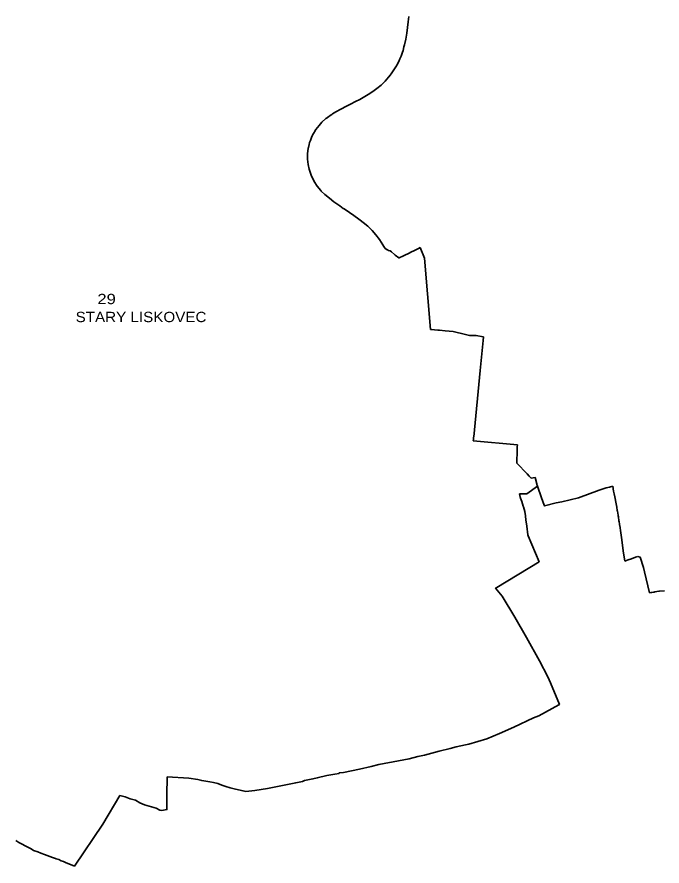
# Model space of a CAD drawing. Extents: x -610940 to -588976, y -1170376 to -1149800.
# Drawn here: x -602206 to -600644, y -1165123 to -1163066 of the extents above; entities that cross this region are included whole.
import ezdxf

# ---------------------------------------------------------------- set-up
doc = ezdxf.new("R2010")
doc.units = 0
doc.header["$LTSCALE"] = 10
doc.layers.add('54', color=7, linetype='Continuous', lineweight=35)
doc.layers.add('55', color=7, linetype='Continuous')
doc.layers.add('56', color=7, linetype='Continuous')

msp = doc.modelspace()

# ---------------------------------------------------------------- linework, layer by layer
at = {"layer": '54'}
for p, q in [((-601281.72, -1163174.04), (-601278.79, -1163167.7)), ((-601298.34, -1163201.91), (-601288.58, -1163187.04)), ((-601314.84, -1163221.81), (-601306.58, -1163212.44)), ((-601306.58, -1163212.44), (-601305.86, -1163211.62)), ((-601305.86, -1163211.62), (-601302.39, -1163207.25)), ((-601302.39, -1163207.25), (-601299.9, -1163204.11)), ((-601299.9, -1163204.11), (-601298.34, -1163201.91)), ((-601334.39, -1163239.6), (-601324.44, -1163231.2)), ((-601324.44, -1163231.2), (-601314.84, -1163221.81)), ((-601376.17, -1163266.1), (-601355.57, -1163254.24)), ((-601355.57, -1163254.24), (-601344.5, -1163247.04)), ((-601344.5, -1163247.04), (-601334.39, -1163239.6)), ((-601410.02, -1163283.2), (-601398.66, -1163277.5)), ((-601398.66, -1163277.5), (-601386.42, -1163271.38)), ((-601386.42, -1163271.38), (-601376.17, -1163266.1)), ((-601441.93, -1163301.26), (-601433.77, -1163296.19)), ((-601433.77, -1163296.19), (-601422.25, -1163289.51)), ((-601422.25, -1163289.51), (-601420.58, -1163288.65)), ((-601420.58, -1163288.65), (-601410.02, -1163283.2)), ((-601474.67, -1163328.87), (-601467.67, -1163321.28)), ((-601467.67, -1163321.28), (-601457.87, -1163312.46)), ((-601457.87, -1163312.46), (-601455.31, -1163310.61)), ((-601495.45, -1163365.24), (-601492.96, -1163358.42)), ((-601492.96, -1163358.42), (-601490.12, -1163352.23)), ((-601490.12, -1163352.23), (-601489.4, -1163350.88)), ((-601486.71, -1163345.94), (-601485.62, -1163344.36)), ((-601497.37, -1163370.7), (-601495.45, -1163365.24)), ((-601502.35, -1163397.75), (-601500.61, -1163383.76)), ((-601502.35, -1163397.75), (-601502.2, -1163411.04)), ((-601502.2, -1163411.04), (-601500.71, -1163424.06)), ((-601500.71, -1163424.06), (-601498.32, -1163435.22)), ((-601498.32, -1163435.22), (-601493.67, -1163449.65)), ((-601493.67, -1163449.65), (-601486.56, -1163464.53)), ((-601486.56, -1163464.53), (-601479.17, -1163475.92)), ((-601479.17, -1163475.92), (-601470.51, -1163486.67)), ((-601460.45, -1163496.63), (-601449.66, -1163505.62)), ((-601449.66, -1163505.62), (-601438.57, -1163514.04)), ((-601438.57, -1163514.04), (-601427.03, -1163522.26)), ((-601401.11, -1163539.91), (-601390.51, -1163547.27)), ((-601378.54, -1163555.92), (-601375.15, -1163558.32)), ((-601356.83, -1163573.41), (-601346.34, -1163583.64)), ((-601346.34, -1163583.64), (-601337.03, -1163594.05)), ((-601337.03, -1163594.05), (-601328.37, -1163605.65)), ((-601328.37, -1163605.65), (-601320.45, -1163617.98)), ((-601243.43, -1163631.9), (-601234.21, -1163627.33)), ((-601234.21, -1163627.33), (-601229.76, -1163625.12)), ((-601229.76, -1163625.12), (-601219.23, -1163650.24)), ((-601306.15, -1163631.93), (-601302.46, -1163632.46)), ((-601302.46, -1163632.46), (-601299.14, -1163635.26)), ((-601299.14, -1163635.26), (-601291.63, -1163641.54)), ((-601291.63, -1163641.54), (-601289.92, -1163642.97)), ((-601289.92, -1163642.97), (-601281.57, -1163649.95)), ((-601270.29, -1163645.04), (-601254.81, -1163637.54)), ((-601252.56, -1163636.43), (-601243.43, -1163631.9)), ((-601219.23, -1163650.24), (-601204.53, -1163823.42)), ((-601194.81, -1163824.24), (-601186.64, -1163825.03)), ((-601169.29, -1163826.52), (-601150.05, -1163828.18)), ((-601150.05, -1163828.18), (-601140.07, -1163830.8)), ((-601140.07, -1163830.8), (-601130.04, -1163833.37)), ((-601130.04, -1163833.37), (-601110.53, -1163838.05)), ((-601110.53, -1163838.05), (-601100.8, -1163837.99)), ((-601100.8, -1163837.99), (-601099.1, -1163837.98)), ((-601093.88, -1163837.89), (-601077.62, -1163840.93)), ((-601084.51, -1163922.95), (-601077.4, -1163850.17)), ((-601077.62, -1163840.93), (-601076.52, -1163841.14)), ((-601077.4, -1163850.17), (-601076.52, -1163841.14)), ((-601100.17, -1164083.3), (-601084.51, -1163922.95)), ((-601101.15, -1164093.31), (-601100.79, -1164089.6)), ((-601101.15, -1164093.31), (-600994.11, -1164103.25)), ((-601100.79, -1164089.6), (-601100.66, -1164088.27)), ((-601100.66, -1164088.27), (-601100.31, -1164084.74)), ((-601100.31, -1164084.74), (-601100.17, -1164083.3)), ((-600995.92, -1164147.3), (-600995.51, -1164136.65)), ((-600995.92, -1164147.3), (-600971.06, -1164173.52)), ((-600971.06, -1164173.52), (-600965.87, -1164178.96)), ((-600965.87, -1164178.96), (-600961.12, -1164183.95)), ((-600961.12, -1164183.95), (-600951.19, -1164182.27)), ((-600951.19, -1164182.27), (-600947.44, -1164197.02)), ((-600946.5, -1164200.75), (-600945.48, -1164203.41)), ((-600945.48, -1164203.41), (-600935.88, -1164231.44)), ((-600779.13, -1164207.45), (-600771.69, -1164205.23)), ((-600771.69, -1164205.23), (-600763.32, -1164202.84)), ((-600763.32, -1164202.84), (-600761.4, -1164215.4)), ((-600846.79, -1164231.41), (-600796.34, -1164212.81)), ((-600796.34, -1164212.81), (-600786.81, -1164209.64)), ((-600786.81, -1164209.64), (-600779.13, -1164207.45)), ((-600935.88, -1164231.44), (-600929.74, -1164249.28)), ((-600900.67, -1164243.71), (-600886.59, -1164240.75)), ((-600886.59, -1164240.75), (-600846.79, -1164231.41)), ((-600758.47, -1164228.76), (-600755.15, -1164245.98)), ((-600755.15, -1164245.98), (-600753.63, -1164254.24)), ((-600753.63, -1164254.24), (-600752.4, -1164262.05)), ((-600744.15, -1164316.08), (-600741.6, -1164332.99)), ((-600741.6, -1164332.99), (-600737.95, -1164359.39)), ((-600737.95, -1164359.39), (-600734.47, -1164384.62)), ((-600734.47, -1164384.62), (-600726.43, -1164381.82)), ((-600726.43, -1164381.82), (-600717.74, -1164378.79)), ((-600717.74, -1164378.79), (-600708.02, -1164375.4)), ((-600708.02, -1164375.4), (-600702.39, -1164373.44)), ((-600702.39, -1164373.44), (-600697.38, -1164374.87)), ((-600697.38, -1164374.87), (-600689.38, -1164400.31)), ((-600689.38, -1164400.31), (-600686.91, -1164410.27)), ((-600686.91, -1164410.27), (-600674.27, -1164461.26)), ((-600674.27, -1164461.26), (-600671.11, -1164460.8)), ((-600671.11, -1164460.8), (-600668.95, -1164460.48)), ((-600668.95, -1164460.48), (-600664.93, -1164459.89)), ((-600664.93, -1164459.89), (-600662.95, -1164459.52)), ((-600662.95, -1164459.52), (-600661.61, -1164459.27)), ((-600661.61, -1164459.27), (-600652.1, -1164457.9)), ((-600652.1, -1164457.9), (-600650.35, -1164457.65)), ((-600650.35, -1164457.65), (-600638.07, -1164456.67))]:
    msp.add_line(p, q, dxfattribs=at)
for points in [[(-601262.28, -1163105.48), (-601260.6, -1163091.33), (-601259, -1163077.86), (-601257.56, -1163065.29)], [(-601267.67, -1163133.48), (-601264.83, -1163119.77), (-601262.28, -1163105.48)], [(-601269.06, -1163138.91), (-601268.41, -1163136.34), (-601267.67, -1163133.48)], [(-601278.79, -1163167.7), (-601276.09, -1163161), (-601272.55, -1163151.27)], [(-601272.55, -1163151.27), (-601271.3, -1163147.32), (-601269.06, -1163138.91)], [(-601288.58, -1163187.04), (-601287.09, -1163184.41), (-601286.3, -1163182.72), (-601281.72, -1163174.04)], [(-601455.31, -1163310.61), (-601454.43, -1163309.98), (-601445.02, -1163303.18)], [(-601445.02, -1163303.18), (-601443.4, -1163302.17), (-601441.93, -1163301.26)], [(-601485.62, -1163344.36), (-601482.17, -1163338.56), (-601474.67, -1163328.87)], [(-601489.4, -1163350.88), (-601488.21, -1163348.68), (-601486.71, -1163345.94)], [(-601500.61, -1163383.76), (-601500.29, -1163382.33), (-601498.77, -1163375.59), (-601497.37, -1163370.7)], [(-601470.51, -1163486.67), (-601469.27, -1163488.37), (-601460.45, -1163496.63)], [(-601427.03, -1163522.26), (-601424.27, -1163524.15), (-601415.91, -1163529.9)], [(-601415.91, -1163529.9), (-601413.63, -1163531.38), (-601401.11, -1163539.91)], [(-601390.51, -1163547.27), (-601390.03, -1163547.6), (-601378.54, -1163555.92)], [(-601375.15, -1163558.32), (-601367.85, -1163563.99), (-601356.83, -1163573.41)], [(-601320.45, -1163617.98), (-601317.82, -1163622.46), (-601314.14, -1163627.04)], [(-601314.14, -1163627.04), (-601313.24, -1163627.72), (-601309.47, -1163630.46)], [(-601309.47, -1163630.46), (-601308.89, -1163630.7), (-601306.15, -1163631.93)], [(-601281.57, -1163649.95), (-601281.15, -1163650.3), (-601280.6, -1163650.04), (-601270.29, -1163645.04)], [(-601254.81, -1163637.54), (-601254.53, -1163637.4), (-601254.27, -1163637.27), (-601252.56, -1163636.43)], [(-601204.53, -1163823.42), (-601203.28, -1163823.59), (-601202.07, -1163823.66), (-601194.81, -1163824.24)], [(-601186.64, -1163825.03), (-601183.22, -1163825.32), (-601169.29, -1163826.52)], [(-601099.1, -1163837.98), (-601097.32, -1163837.97), (-601093.88, -1163837.89)], [(-600995.51, -1164136.65), (-600995.09, -1164125.66), (-600994.97, -1164119.4), (-600994.94, -1164117.48), (-600994.86, -1164113.73), (-600994.8, -1164110.34), (-600994.61, -1164107.74), (-600994.11, -1164103.25)], [(-600945.48, -1164203.41), (-600971.54, -1164221.54), (-600982.55, -1164221.54), (-600989.11, -1164221.92), (-600987.81, -1164229.73), (-600987.03, -1164231.18), (-600986.52, -1164232.12), (-600985.4, -1164235.8), (-600983.39, -1164240.58), (-600982.04, -1164245.6), (-600980.26, -1164251.72), (-600979.53, -1164252.76), (-600976.64, -1164264.22), (-600975.02, -1164274.77), (-600973.76, -1164285.51), (-600973.06, -1164289.81), (-600971.61, -1164300.37), (-600968.71, -1164320.86), (-600968.45, -1164323.08), (-600941.69, -1164386.13), (-601044.45, -1164448.46), (-601047.2, -1164450.32), (-601031.39, -1164469.75), (-601000.26, -1164520.81), (-600972.69, -1164569.48), (-600941.03, -1164626.24), (-600920.85, -1164665.1), (-600913.97, -1164679.51), (-600892.76, -1164731.82), (-600894.38, -1164733), (-600942.75, -1164759.17), (-600955.28, -1164764.82), (-601003, -1164787.27), (-601037.51, -1164802.73), (-601068.15, -1164814.91), (-601112.16, -1164828.18), (-601119.73, -1164829.85), (-601142.74, -1164834.99), (-601157.02, -1164838.57), (-601184.1, -1164845.28)], [(-600947.44, -1164197.02), (-600947.03, -1164198.65), (-600946.5, -1164200.75)], [(-600761.4, -1164215.4), (-600759.72, -1164221.59), (-600758.47, -1164228.76)], [(-600929.74, -1164249.28), (-600928.9, -1164250.92), (-600900.67, -1164243.71)], [(-600752.4, -1164262.05), (-600752.13, -1164263.78), (-600750.57, -1164273.06), (-600750.21, -1164275.23), (-600749.91, -1164277.18), (-600748.37, -1164287.07)], [(-600748.37, -1164287.07), (-600747.81, -1164289.32), (-600747.35, -1164294.48)], [(-600747.35, -1164294.48), (-600746.89, -1164297.44), (-600746.69, -1164298.75), (-600744.15, -1164316.08)], [(-601184.1, -1164845.28), (-601219.65, -1164854.82), (-601235.8, -1164858.24), (-601256.27, -1164863.87), (-601281.99, -1164868.54), (-601329.63, -1164877.64), (-601348.03, -1164882.58), (-601376.78, -1164888.57), (-601415.28, -1164896.55), (-601426.23, -1164898.07), (-601426.03, -1164899.11), (-601436.06, -1164900.89), (-601455.87, -1164904.42), (-601478.99, -1164909.95), (-601489.29, -1164912.34), (-601509.88, -1164916.65), (-601514.94, -1164918.44), (-601531.02, -1164921.65), (-601599.57, -1164935.92), (-601630.49, -1164940.54), (-601652.2, -1164942.74), (-601658.57, -1164941.58), (-601669.4, -1164939.22), (-601680.03, -1164936.68), (-601690.02, -1164934), (-601700.59, -1164930.92), (-601705.57, -1164928.99), (-601710.18, -1164927.49), (-601719.94, -1164923.93), (-601730.13, -1164921.23), (-601738.89, -1164919.76), (-601758.75, -1164916.4), (-601768.28, -1164914.04), (-601789.6, -1164911), (-601842.2, -1164907.41), (-601843.16, -1164951.68), (-601843.06, -1164983.61), (-601842.88, -1164986.78), (-601854.98, -1164988.76), (-601860.46, -1164988)], [(-601860.46, -1164988), (-601868.95, -1164983.18), (-601896.97, -1164975.6), (-601908.19, -1164970.18), (-601919.03, -1164964.19), (-601931.73, -1164960.49), (-601944.22, -1164955.99), (-601956.68, -1164952.66), (-601998.54, -1165022.14), (-602067.07, -1165123.48), (-602088.51, -1165114.81), (-602093.68, -1165112.5), (-602099.15, -1165110.57), (-602104.94, -1165108.08), (-602111.21, -1165106.02), (-602113, -1165105.43), (-602120.33, -1165102.66), (-602132.95, -1165097.89), (-602139.61, -1165095.38), (-602148.18, -1165092.13), (-602155.53, -1165089.36), (-602165.77, -1165085.48), (-602172.05, -1165082.07), (-602186.09, -1165074.42), (-602193.78, -1165070.24), (-602201.38, -1165066.1), (-602208.95, -1165061.98)]]:
    msp.add_lwpolyline(points, dxfattribs=at)

# ---------------------------------------------------------------- texts
at = {"layer": '55', "width": 1.1}
msp.add_text('STARY LISKOVEC', height=25, dxfattribs=at).set_placement((-602064.04, -1163805.64))
at = {"layer": '56', "width": 1.2}
msp.add_text('29 ', height=25, dxfattribs=at).set_placement((-602011.35, -1163762.06))

doc.saveas('drawing.dxf')
